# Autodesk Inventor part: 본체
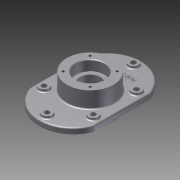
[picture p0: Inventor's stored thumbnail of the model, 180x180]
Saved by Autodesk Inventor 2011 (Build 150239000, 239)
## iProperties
Created: 2015-02
Part Number: 본체
Document SubType Name: Modeling
Designer: Administrator
Density: 1 g/cm^3
Author: Administrator
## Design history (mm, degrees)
sketch "스케치1"
  geometry: L1 (-70, 60)-(70, 60); L2 (70, 60)-(70, -60); L3 (70, -60)-(-70, -60); L4 (-70, -60)-(-70, 60); L5 (0, 60)-(0, 110); L6 (0, -60)-(0, -110); A1 r 74 centre (0, 36) between (70, 60) and (-70, 60); A2 r 74 centre (0, -36) between (-70, -60) and (70, -60); 3 further points
  constraints: 12 end point, 6 point on circle, 3 midpoint, 2 centre point, 1 coincident, 1 horizontal alignment, 1 vertical alignment
  dimensions: "d1" = 140 distance of L1.start L1.end; "d2" = 120 distance of L3.end L1.start; "d3" = 50 distance of L5.start L5.end; "d4" = 50 distance of L6.start L6.end; "d5" = 220 distance of L6.end L5.end
extrude "돌출1" new body sketch "스케치1" distance "d6" = 12; taper "d7" = 0 deg
sketch "스케치2"
  geometry: C1 r 50 at (0, 0); 1 further point
  constraints: 1 centre point, 1 coincident
  dimensions: "d8" = 100 diameter of C1
extrude "돌출2" join sketch "스케치2" distance "d9" = 35; taper "d10" = 0 deg
sketch "스케치3"
  geometry: C1 r 50 at (0, 0); 1 further point
  constraints: 1 centre point, 1 coincident
  dimensions: "d11" = 100 diameter of C1
extrude "돌출3" join sketch "스케치3" distance "d12" = 23; taper "d13" = 0 deg
sketch "스케치4"
  geometry: C1 r 50 at (0, 0) reference; C2 r 31 at (0, 0)
  constraints: 1 centre point, 1 coincident
  dimensions: "d14" = 62 diameter of C2
extrude "돌출4" cut sketch "스케치4" distance "d15" = 22; taper "d16" = 0 deg
sketch "스케치5"
  geometry: C1 r 50 at (0, 0) reference; C2 r 31 at (0, 0)
  constraints: 1 centre point, 1 coincident
  dimensions: "d17" = 62 diameter of C2
extrude "돌출5" cut sketch "스케치5" distance "d18" = 22; taper "d19" = 0 deg
sketch "스케치6"
  geometry: C1 r 31 at (0, 0) reference; C2 r 22.5 at (0, 0)
  constraints: 1 centre point, 1 coincident
  dimensions: "d20" = 45 diameter of C2
extrude "돌출6" cut sketch "스케치6" stored distance "d21" = 22; taper "d22" = 0 deg
sketch "스케치7"
  geometry: L1 (0, 0)-(0, 41); L2 (0, 0)-(28.991, 28.991); C1 r 50 at (0, 0) reference; A1 r 41 centre (0, 0) between (0, 41) and (28.991, 28.991); 1 further point
  constraints: 4 end point, 2 coincident, 2 point on circle, 1 centre point, 1 vertical
  dimensions: "d23" = 82 diameter of A1; "d24" = 45 deg angle of L2 L1
hole "Hole1" sketch "스케치7" at (28.991, 28.991) diameter "d25" = 4.917; stored, may be unused: countersink angle "d29" = 90 deg, drill point angle "d31" = 118 deg; dims "d26" = 10, "d27" = 4, "d28" = 2, "d30" = 13
sketch "스케치8"
  geometry: L1 (0, 0)-(28.991, 28.991); L2 (0, 41)-(0, 0); C1 r 31 at (0, 0) reference; C2 r 50 at (0, 0) reference; A1 r 41 centre (0, 0) between (28.991, 28.991) and (0, 41); 1 further point
  constraints: 4 end point, 3 coincident, 2 point on circle, 1 centre point, 1 vertical
  dimensions: "d35" = 82 diameter of A1; "d36" = 45 deg angle of L1 L2
hole "Hole2" sketch "스케치8" at (28.991, 28.991) diameter "d37" = 4.917; stored, may be unused: countersink angle "d41" = 90 deg, drill point angle "d43" = 118 deg; dims "d38" = 10, "d39" = 4, "d40" = 2, "d42" = 13
sketch "스케치9"
  geometry: L1 (-70, -60)-(-70, 60) reference; L2 (70, 60)-(70, -60) reference; L3 (-53, 60)-(-53, -60); L4 (53, 60)-(53, -60); L5 (0, -110)-(0, -93); L6 (0, 110)-(0, 93); L7 (-80.54, 46.5)-(-53, 46.5); L8 (-80.54, -46.5)-(-53, -46.5); L9 (80.54, 46.5)-(53, 46.5); L10 (80.54, -46.5)-(53, -46.5); C1 r 50 at (0, 0) reference; C2 r 10 at (0, 93); C3 r 10 at (0, -93); C4 r 10 at (-80.54, 46.5); C5 r 10 at (-80.54, -46.5); C6 r 10 at (0, -93); C7 r 10 at (80.54, -46.5); C8 r 10 at (80.54, 46.5); C9 r 10 at (-53, 46.5); C10 r 10 at (-53, -46.5); C11 r 10 at (53, 46.5); C12 r 10 at (53, -46.5); A1 r 74 centre (0, 36) between (70, 60) and (-70, 60) reference; A2 r 74 centre (0, -36) between (-70, -60) and (70, -60) reference; A3 r 59.061 centre (0, 33.939) between (53, 60) and (-53, 60); A4 r 59.061 centre (0, -33.939) between (-53, -60) and (53, -60); 2 further points
  constraints: 16 end point, 13 centre point, 8 point on circle, 6 coincident, 4 point on line, 2 horizontal alignment, 2 midpoint, 1 vertical, 13 other
  dimensions: "d47" = 120 distance of L3.start L3.end; "d48" = 17 distance between parallel lines of L3 L1; "d49" = 17 distance between parallel lines of L2 L4; "d50" = 120 distance of L4.start L4.end; "d51" = 17 distance of L5.start L5.end; "d52" = 17 distance of L6.start L6.end; "d53" = 20 diameter of C2; "d54" = 20 diameter of C3; "d57" = 360 deg dimension on C1.centre C2.centre (derived); "d59" = 20 diameter of C9; "d60" = 20 diameter of C11; "d61" = 20 diameter of C10; "d63" = 20 diameter of C12
extrude "돌출7" join sketch "스케치9" distance "d64" = 5; taper "d65" = 0 deg
sketch "스케치10"
  geometry: C1 r 10 at (0, 0) reference; C2 r 10 at (-53, -46.5) reference; C3 r 10 at (-53, -139.5) reference; C4 r 10 at (0, -186) reference; C5 r 10 at (53, -139.5) reference; C6 r 10 at (53, -46.5) reference; 7 further points
  constraints: 6 coincident
hole "Hole3" sketch "스케치10" at (0, 0), (-53, -46.5), (-53, -139.5), (0, -186), (53, -139.5), (53, -46.5) diameter "d66" = 11; stored, may be unused: countersink angle "d70" = 90 deg, drill point angle "d72" = 118 deg; dims "d67" = 10, "d68" = 4, "d69" = 2, "d71" = 13
fillet "모깎기1" dims "d73" = 0.3
chamfer "모따기1" distance "d74" = 1; stored, may be unused: second distance "d75" = 2, angle "d76" = 45 deg
fillet "모깎기3" dims "d78" = 3
sketch "스케치11"
  geometry: L1 (-33.101, 69.803)-(33.101, 69.803); L2 (33.101, 69.803)-(33.101, 60.197); L3 (33.101, 60.197)-(-33.101, 60.197); L4 (-33.101, 60.197)-(-33.101, 69.803); L5 (-33.101, 65)-(33.101, 65); C1 r 53 at (0, 0) reference; 2 further points
  constraints: 3 midpoint, 2 end point, 2 vertical alignment, 2 other
  dimensions: "d79" = 65 vertical distance of C1.centre L5.start
feature "엠보싱1" sketch "스케치11" dims "d1" = 140, "d80" = 1, "d81" = 0
fillet "모깎기4" dims "d82" = 3
node "솔리드1"
pattern_circular "원형 패턴1" dims angle "d33" = 360 deg
pattern_circular "원형 패턴2" dims angle "d45" = 360 deg
node "투영된 루프1"
node "투영된 루프2"
node "투영된 루프3"
node "투영된 루프4"
